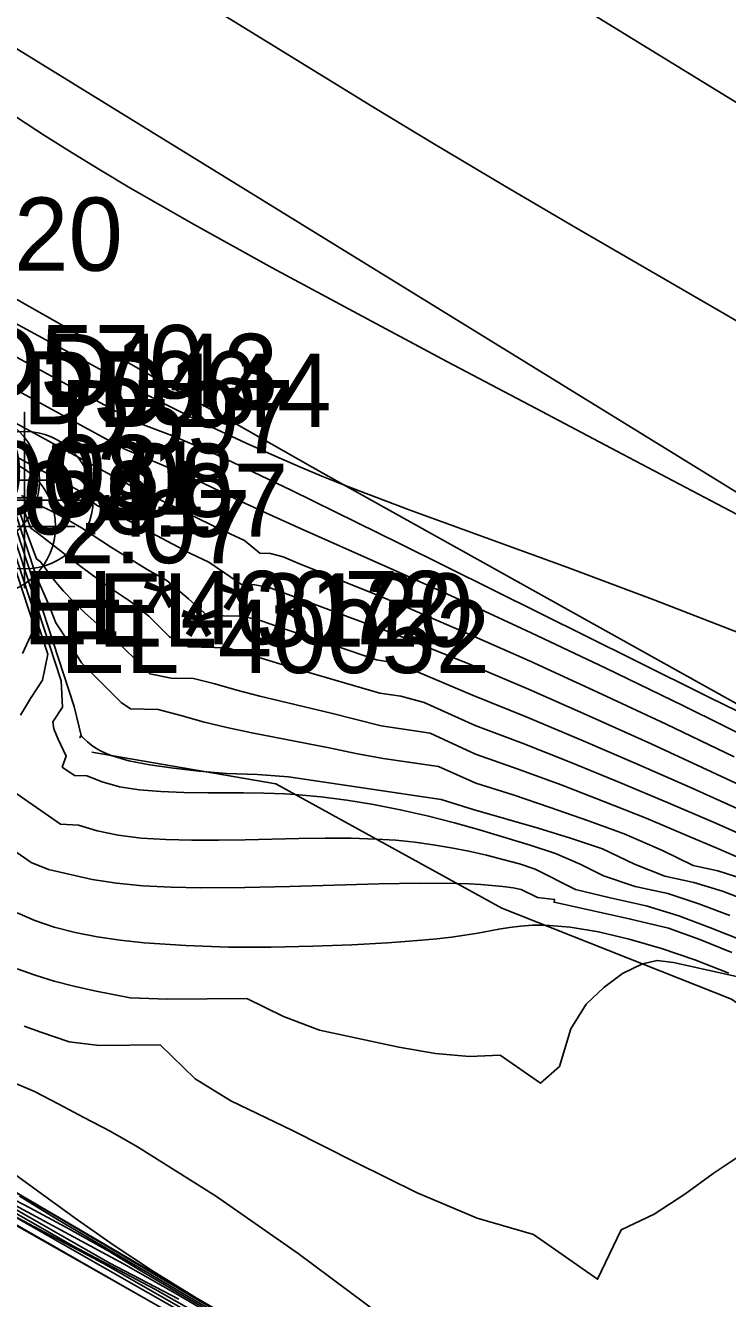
# Model space of a CAD drawing. Extents: x 2356077 to 2359823, y 225951 to 227822.
# Drawn here: x 2357233.67 to 2357257.64, y 226874.84 to 226918.29 of the extents above; entities that cross this region are included whole.
import ezdxf

# ---------------------------------------------------------------- set-up
doc = ezdxf.new("R2010")
doc.units = 0
for name, color, linetype in [('DTM Contours Major', 7, 'Continuous'), ('DTM Contours Minor', 7, 'Continuous'), ('Exist DTM Breakline', 7, 'Continuous'), ('Exist DTM Breakline Cogo Comment', 7, 'Continuous'), ('Exist DTM Breakline Cogo Elevation', 7, 'Continuous'), ('Exist DTM Breakline Cogo Number', 7, 'Continuous'), ('Exist DTM Breakline Cogo Point CELL', 7, 'Continuous'), ('Exist DTM Breakline Underwater', 7, 'Continuous'), ('Exist DTM Breakline Underwater Cogo Comment', 7, 'Continuous'), ('Exist DTM Breakline Underwater Cogo Elevation', 7, 'Continuous'), ('Exist DTM Breakline Underwater Cogo Number', 7, 'Continuous'), ('Exist DTM Breakline Underwater Cogo Point CELL', 7, 'Continuous'), ('Exist DTM Crownline', 7, 'Continuous'), ('Exist DTM Drainline Cogo Comment', 7, 'Continuous'), ('Exist DTM Regular Point Underwater Cogo Elevation', 7, 'Continuous'), ('Exist DTM Regular Point Underwater Cogo Number', 7, 'Continuous'), ('Exist Roads EOP', 7, 'Continuous'), ('Exist Structure Minor Head and End Wall Cogo Comment', 7, 'Continuous'), ('Exist Structure Minor Head and End Wall Cogo Elevation', 7, 'Continuous'), ('Exist Structure Minor Head and End Wall Cogo Number', 7, 'Continuous'), ('Exist Structure Minor Head and End Wall Cogo Point CELL', 7, 'Continuous'), ('PH Exist DTM Breakline', 7, 'Continuous')]:
    doc.layers.add(name, color=color, linetype=linetype)

msp = doc.modelspace()

# ---------------------------------------------------------------- linework, layer by layer
at = {"layer": 'DTM Contours Major'}
for points in [[(2357259.379, 226894.199), (2357257.032, 226895.35), (2357254.467, 226896.62), (2357246.438, 226900.61), (2357242.768, 226902.412), (2357241.175, 226903.182), (2357240.357, 226903.564), (2357239.952, 226903.748), (2357238.667, 226904.296), (2357237.424, 226904.758), (2357230.879, 226908.313)], [(2357258.086, 226890.681), (2357257.192, 226891.086), (2357255.615, 226891.755), (2357253.983, 226892.439), (2357252.322, 226893.12), (2357250.661, 226893.778), (2357249.025, 226894.395), (2357247.279, 226895.175), (2357246.489, 226895.394), (2357245.768, 226895.501), (2357242.718, 226896.389), (2357241.977, 226896.61), (2357240.569, 226897.049), (2357239.237, 226897.085), (2357238.588, 226897.424), (2357237.887, 226898.121), (2357237.225, 226898.649), (2357236.574, 226899.081), (2357235.959, 226899.521), (2357235.376, 226899.96), (2357234.046, 226900.989), (2357233.856, 226901.132), (2357233.621, 226901.724)], [(2357233.499, 226894.751), (2357233.838, 226895.313), (2357234.246, 226895.936), (2357234.435, 226896.825), (2357232.944, 226901.378)], [(2357258.155, 226887.055), (2357257.065, 226887.491), (2357255.983, 226887.896), (2357254.867, 226888.242), (2357253.64, 226888.515), (2357252.457, 226888.802), (2357251.078, 226889.494), (2357250.536, 226889.668), (2357249.973, 226889.822), (2357249.413, 226889.963), (2357248.81, 226890.1), (2357248.203, 226890.221), (2357247.588, 226890.324), (2357246.96, 226890.409), (2357246.313, 226890.475), (2357245.644, 226890.52), (2357244.791, 226890.548), (2357243.907, 226890.551), (2357243.002, 226890.538), (2357241.17, 226890.493), (2357240.264, 226890.476), (2357239.346, 226890.475), (2357238.46, 226890.498), (2357237.62, 226890.553), (2357236.836, 226890.649), (2357236.12, 226890.794), (2357235.484, 226890.997), (2357234.861, 226891.021), (2357233.077, 226892.261)], [(2357245.841, 226874.248), (2357242.983, 226876.373), (2357240.158, 226878.343), (2357237.493, 226880.018), (2357236.559, 226880.544), (2357235.665, 226881.019), (2357234.805, 226881.464), (2357233.979, 226881.899), (2357233.205, 226882.233)], [(2357238.268, 226874.546), (2357229.529, 226879.532)], [(2357240.511, 226874.001), (2357238.784, 226875.014), (2357237.012, 226876.025), (2357233.304, 226878.019)]]:
    msp.add_lwpolyline(points, dxfattribs=at)
at = {"layer": 'DTM Contours Minor'}
for points in [[(2357258.815, 226901.155), (2357254.058, 226903.658), (2357251.108, 226905.209), (2357248.057, 226906.82), (2357245.016, 226908.442), (2357242.096, 226910.021), (2357239.409, 226911.507), (2357238.293, 226912.138), (2357237.237, 226912.748), (2357236.23, 226913.344), (2357235.262, 226913.935), (2357234.32, 226914.53), (2357233.395, 226915.136), (2357232.729, 226915.587), (2357231.377, 226916.526), (2357229.955, 226917.523), (2357229.2, 226918.046), (2357226.653, 226919.767)], [(2357260.038, 226906.976), (2357257.54, 226908.44), (2357252.514, 226911.361), (2357250.026, 226912.818), (2357247.581, 226914.271), (2357245.68, 226915.422), (2357240.031, 226918.889)], [(2357258.266, 226897.467), (2357255.166, 226898.675), (2357252.154, 226899.796), (2357246.767, 226901.757), (2357244.581, 226902.586), (2357243.794, 226902.902), (2357243.061, 226903.209), (2357241.967, 226903.688), (2357241.2, 226904.036), (2357239.517, 226904.819), (2357237.877, 226905.644), (2357230.432, 226909.689)], [(2357238.901, 226874.819), (2357236.525, 226876.052), (2357229.684, 226879.956), (2357224.75, 226882.878), (2357223.73, 226883.469), (2357223.037, 226884.013), (2357219.781, 226885.873), (2357219.03, 226886.387), (2357229.069, 226899.479), (2357230.892, 226901.945), (2357230.985, 226902.237), (2357231.039, 226902.209), (2357229.028, 226903.4), (2357226.593, 226904.852), (2357225.975, 226905.198), (2357219.406, 226908.954)], [(2357258.802, 226893.741), (2357256.134, 226895.069), (2357253.488, 226896.352), (2357250.939, 226897.559), (2357248.564, 226898.658), (2357246.438, 226899.618), (2357242.976, 226901.147), (2357241.872, 226901.649), (2357241.06, 226902.031), (2357239.718, 226902.675), (2357239.276, 226902.88), (2357238.834, 226903.079), (2357237.059, 226903.823), (2357231.766, 226906.699)], [(2357257.871, 226893.324), (2357255.546, 226894.436), (2357253.199, 226895.534), (2357250.898, 226896.586), (2357248.711, 226897.558), (2357246.705, 226898.419), (2357245.525, 226898.907), (2357242.948, 226899.951), (2357242.473, 226900.146), (2357242.041, 226900.269), (2357241.667, 226900.278), (2357241.145, 226900.707), (2357240.175, 226901.166), (2357238.617, 226901.93), (2357238.12, 226902.167), (2357237.632, 226902.388), (2357236.995, 226902.724), (2357232.432, 226905.204)], [(2357259.072, 226891.891), (2357257.097, 226892.816), (2357255.032, 226893.766), (2357252.931, 226894.714), (2357250.848, 226895.629), (2357248.837, 226896.484), (2357246.232, 226897.539), (2357245.579, 226897.777), (2357243.71, 226898.468), (2357242.55, 226898.897), (2357241.99, 226899.109), (2357241.498, 226899.197), (2357241.041, 226899.209), (2357240.464, 226899.608), (2357239.933, 226899.965), (2357239.302, 226900.269), (2357238.698, 226900.578), (2357237.046, 226901.454), (2357236.55, 226901.701), (2357236.096, 226901.911), (2357235.525, 226902.39), (2357233.193, 226903.657)], [(2357258.888, 226891.152), (2357256.355, 226892.285), (2357254.515, 226893.095), (2357252.639, 226893.905), (2357250.767, 226894.69), (2357248.939, 226895.427), (2357247.082, 226896.209), (2357246.269, 226896.533), (2357245.655, 226896.637), (2357244.217, 226897.122), (2357242.873, 226897.568), (2357242.205, 226897.795), (2357241.56, 226898.02), (2357240.985, 226898.124), (2357239.876, 226898.154), (2357239.238, 226898.717), (2357238.493, 226899.344), (2357237.824, 226899.722), (2357237.195, 226900.103), (2357236.61, 226900.474), (2357235.577, 226901.137), (2357235.093, 226901.428), (2357234.869, 226901.554), (2357234.654, 226901.668), (2357234.448, 226901.769), (2357234.248, 226901.86), (2357233.92, 226902.126), (2357233.798, 226902.161), (2357233.712, 226902.153), (2357233.53, 226902.245)], [(2357258.196, 226889.812), (2357257.251, 226890.22), (2357256.331, 226890.602), (2357254.862, 226891.235), (2357253.42, 226891.805), (2357251.958, 226892.367), (2357250.492, 226892.908), (2357249.037, 226893.413), (2357247.494, 226894.132), (2357246.662, 226894.262), (2357245.816, 226894.388), (2357244.107, 226894.81), (2357241.671, 226895.398), (2357240.888, 226895.6), (2357240.137, 226895.811), (2357239.411, 226895.994), (2357238.643, 226896.014), (2357237.912, 226896.157), (2357236.557, 226897.504), (2357236.112, 226897.864), (2357235.694, 226898.237), (2357235.305, 226898.622), (2357234.971, 226898.984), (2357234.654, 226899.35), (2357234.185, 226899.983), (2357234.046, 226900.081), (2357233.681, 226901.057), (2357233.456, 226901.746)], [(2357233.569, 226896.857), (2357233.976, 226897.744), (2357232.803, 226901.326)], [(2357257.719, 226887.91), (2357256.666, 226888.312), (2357255.602, 226888.656), (2357254.487, 226888.904), (2357253.413, 226889.259), (2357252.609, 226889.661), (2357251.766, 226890.022), (2357250.9, 226890.306), (2357250.037, 226890.577), (2357249.177, 226890.834), (2357248.317, 226891.073), (2357247.39, 226891.308), (2357246.466, 226891.516), (2357245.55, 226891.695), (2357244.645, 226891.843), (2357243.755, 226891.957), (2357242.883, 226892.036), (2357242.522, 226892.058), (2357241.811, 226892.086), (2357241.112, 226892.097), (2357239.909, 226892.101), (2357239.079, 226892.109), (2357238.289, 226892.137), (2357237.553, 226892.198), (2357236.883, 226892.306), (2357236.292, 226892.475), (2357235.766, 226892.672), (2357235.344, 226892.683), (2357234.926, 226892.973), (2357235.057, 226893.344), (2357234.769, 226893.947), (2357234.642, 226894.281), (2357234.601, 226894.524), (2357234.928, 226895.022), (2357234.888, 226895.923), (2357233.08, 226901.445)], [(2357258.455, 226888.36), (2357257.472, 226888.744), (2357256.495, 226889.035), (2357255.497, 226889.257), (2357254.469, 226889.665), (2357253.379, 226890.186), (2357252.285, 226890.543), (2357251.179, 226890.885), (2357248.958, 226891.528), (2357247.866, 226891.871), (2357242.65, 226892.646), (2357241.591, 226892.722), (2357240.53, 226892.752), (2357239.596, 226892.838), (2357238.719, 226892.933), (2357237.915, 226893.048), (2357237.201, 226893.192), (2357236.593, 226893.375), (2357236.406, 226893.452), (2357236.232, 226893.535), (2357236.072, 226893.626), (2357235.924, 226893.726), (2357235.786, 226893.834), (2357235.657, 226893.953), (2357235.606, 226894.004), (2357235.565, 226894.039), (2357235.527, 226893.983), (2357235.574, 226894.054), (2357235.334, 226895.043), (2357233.199, 226901.563)], [(2357258.17, 226889.16), (2357257.317, 226889.43), (2357256.473, 226889.618), (2357255.42, 226890.123), (2357254.117, 226890.697), (2357252.86, 226891.155), (2357251.592, 226891.601), (2357250.318, 226892.027), (2357249.046, 226892.423), (2357247.768, 226892.992), (2357245.889, 226893.271), (2357244.954, 226893.443), (2357244.042, 226893.628), (2357241.397, 226894.142), (2357240.547, 226894.322), (2357239.736, 226894.517), (2357238.969, 226894.738), (2357238.201, 226894.94), (2357237.257, 226894.965), (2357236.942, 226895.183), (2357235.586, 226896.531), (2357235.173, 226897.198), (2357234.711, 226897.893), (2357234.465, 226898.51), (2357234.044, 226899.467), (2357233.332, 226901.641)], [(2357257.79, 226886.644), (2357256.698, 226887.085), (2357255.624, 226887.48), (2357254.289, 226887.792), (2357251.721, 226888.363), (2357251.74, 226888.456), (2357251.152, 226888.521), (2357250.592, 226888.802), (2357250.321, 226888.851), (2357249.966, 226888.896), (2357249.6, 226888.933), (2357249.22, 226888.964), (2357248.822, 226888.987), (2357248.404, 226889.004), (2357247.139, 226889.016), (2357245.737, 226888.992), (2357242.702, 226888.899), (2357241.159, 226888.863), (2357239.659, 226888.855), (2357238.645, 226888.877), (2357237.682, 226888.927), (2357236.778, 226889.013), (2357235.941, 226889.14), (2357234.45, 226889.483), (2357233.858, 226889.722), (2357231.329, 226891.479)], [(2357257.688, 226885.942), (2357256.531, 226886.393), (2357255.388, 226886.783), (2357254.282, 226887.103), (2357253.237, 226887.347), (2357252.273, 226887.507), (2357251.415, 226887.576), (2357250.981, 226887.574), (2357250.578, 226887.545), (2357250.2, 226887.498), (2357249.836, 226887.438), (2357249.116, 226887.306), (2357248.675, 226887.235), (2357248.212, 226887.172), (2357247.721, 226887.117), (2357247.197, 226887.067), (2357246.634, 226887.021), (2357246.027, 226886.979), (2357244.814, 226886.91), (2357243.48, 226886.857), (2357242.064, 226886.828), (2357240.607, 226886.833), (2357239.147, 226886.881), (2357237.725, 226886.981), (2357236.903, 226887.07), (2357236.113, 226887.185), (2357235.362, 226887.331), (2357234.654, 226887.513), (2357233.994, 226887.735), (2357233.387, 226888.001)], [(2357258.155, 226885.777), (2357255.801, 226886.301), (2357255.237, 226886.375), (2357254.739, 226886.26), (2357254.057, 226885.925), (2357253.424, 226885.446), (2357252.812, 226884.888), (2357252.288, 226884.037), (2357251.902, 226882.751), (2357251.257, 226882.186), (2357249.883, 226883.141), (2357248.827, 226883.091), (2357247.67, 226883.2), (2357246.424, 226883.419), (2357243.705, 226883.992), (2357242.479, 226884.467), (2357241.23, 226885.08), (2357238.515, 226885.049), (2357237.247, 226885.096), (2357236.027, 226885.338), (2357235.323, 226885.498), (2357234.645, 226885.673), (2357233.997, 226885.868), (2357233.38, 226886.085)], [(2357258.104, 226879.736), (2357257.158, 226879.107), (2357256.18, 226878.398), (2357255.141, 226877.72), (2357254.012, 226877.185), (2357253.207, 226875.493), (2357251.017, 226877.023), (2357249.092, 226877.58), (2357247.043, 226878.444), (2357244.923, 226879.486), (2357242.783, 226880.574), (2357240.678, 226881.578), (2357239.469, 226882.331), (2357238.265, 226883.498), (2357236.183, 226883.473), (2357235.166, 226883.595), (2357234.189, 226883.926), (2357233.624, 226884.127)], [(2357247.889, 226869.874), (2357230.089, 226880.364)], [(2357243.5, 226872.067), (2357238.081, 226875.159), (2357235.263, 226876.645), (2357229.64, 226879.853)], [(2357249.67, 226868.677), (2357237.633, 226875.771), (2357236.491, 226876.467), (2357235.169, 226877.205), (2357233.813, 226877.936), (2357232.345, 226878.694)], [(2357241.876, 226873.478), (2357239.502, 226874.855), (2357238.012, 226875.782), (2357236.669, 226876.672), (2357235.45, 226877.523), (2357234.331, 226878.33), (2357233.288, 226879.09)], [(2357248.787, 226869.271), (2357234.761, 226877.537), (2357233.464, 226878.324)], [(2357245.888, 226870.576), (2357236.329, 226876.031), (2357233.252, 226877.664)], [(2357248.292, 226869.077), (2357233.41, 226877.569)]]:
    msp.add_lwpolyline(points, dxfattribs=at)
at = {"layer": 'Exist DTM Breakline'}
msp.add_lwpolyline([(2357271.839, 226810.793), (2357233.688, 226822.752), (2357256.15, 226865.111), (2357219.602, 226886.502), (2357232.348, 226901.185)], dxfattribs=at)
at = {"layer": 'Exist DTM Breakline Cogo Point CELL'}
msp.add_lwpolyline([(2357232.348, 226904.185), (2357232.348, 226898.185), (2357232.348, 226901.185), (2357235.348, 226901.185), (2357229.348, 226901.185)], dxfattribs=at)
msp.add_circle((2357232.348, 226901.185), 2.344, dxfattribs=at)
at = {"layer": 'Exist DTM Breakline Underwater'}
msp.add_lwpolyline([(2357271.485, 226810.176), (2357230.992, 226822.359), (2357255.147, 226864.969), (2357217.975, 226886.043), (2357231.073, 226902.169)], dxfattribs=at)
at = {"layer": 'Exist DTM Breakline Underwater Cogo Point CELL'}
msp.add_lwpolyline([(2357231.073, 226905.169), (2357231.073, 226899.169), (2357231.073, 226902.169), (2357234.073, 226902.169), (2357228.073, 226902.169)], dxfattribs=at)
at = {"layer": 'Exist DTM Crownline'}
msp.add_lwpolyline([(2357542.756, 226741.609), (2357459.889, 226792.427), (2357374.177, 226844.74), (2357291.426, 226895.083), (2357208.118, 226946.275), (2357125.882, 226996.539), (2357045.017, 227045.595), (2356966.337, 227093.498), (2356883.413, 227143.712), (2356799.704, 227194.618), (2356722.637, 227241.528), (2356636.765, 227293.74), (2356553.053, 227344.465), (2356470.397, 227394.758), (2356383.201, 227447.638), (2356299.889, 227498.478), (2356223.248, 227545.375)], dxfattribs=at)
at = {"layer": 'Exist Roads EOP'}
msp.add_lwpolyline([(2357548.158, 226751.097), (2357551.518, 226748.955), (2357539.932, 226730.044), (2357536.732, 226732.588), (2357457.094, 226780.918), (2357368.575, 226834.971), (2357285.95, 226885.112), (2357202.56, 226936.462), (2357119.743, 226986.718), (2357040.047, 227034.838), (2356959.55, 227083.993), (2356876.77, 227134.388), (2356794.33, 227184.148), (2356716.529, 227232.438), (2356632.17, 227283.448), (2356547.589, 227334.799), (2356465.16, 227384.805), (2356376.528, 227438.798), (2356293.908, 227488.913), (2356217.843, 227535.566)], dxfattribs=at)
at = {"layer": 'Exist Structure Minor Head and End Wall Cogo Point CELL'}
for points in [[(2357228.808, 226902.763), (2357234.808, 226902.763), (2357231.808, 226902.763), (2357231.808, 226905.763), (2357231.808, 226899.763)], [(2357230.633, 226902.085), (2357236.633, 226902.085), (2357233.633, 226902.085), (2357233.633, 226905.085), (2357233.633, 226899.085)]]:
    msp.add_lwpolyline(points, dxfattribs=at)
for centre in [(2357231.808, 226902.763), (2357233.633, 226902.085)]:
    msp.add_circle(centre, 2.344, dxfattribs=at)
at = {"layer": 'PH Exist DTM Breakline'}
for points in [[(2357134.751, 226970.426), (2357158.028, 226955.6), (2357176.952, 226945.122), (2357197.905, 226932.262), (2357212.892, 226921.066), (2357229.01, 226911.408), (2357243.825, 226903.007), (2357264.516, 226891.487), (2357285.525, 226878.969), (2357309.065, 226864.903), (2357332.833, 226850.108), (2357352.43, 226838.187), (2357373.686, 226825.25), (2357394.277, 226813), (2357414.012, 226801.184), (2357434.963, 226788.955), (2357455.092, 226776.87), (2357475.043, 226763.829)], [(2357329.327, 226839.832), (2357322.093, 226843.761), (2357315.282, 226847.511), (2357308.493, 226851.773), (2357300.459, 226857.57), (2357292.502, 226862.082), (2357284.62, 226866.884), (2357274.115, 226873.82), (2357265.28, 226880.04), (2357257.777, 226885.056), (2357249.936, 226888.163), (2357242.214, 226892.404), (2357235.933, 226893.489)]]:
    msp.add_lwpolyline(points, dxfattribs=at)

# ---------------------------------------------------------------- texts
at = {"layer": 'Exist DTM Breakline Cogo Comment'}
msp.add_text('EL*40052', height=2.5, dxfattribs=at).set_placement((2357234.848, 226896.185))
at = {"layer": 'Exist DTM Breakline Cogo Elevation'}
msp.add_text('2.07', height=2.5, dxfattribs=at).set_placement((2357234.848, 226899.935))
at = {"layer": 'Exist DTM Breakline Cogo Number'}
msp.add_text('D597', height=2.5, dxfattribs=at).set_placement((2357234.848, 226903.685))
at = {"layer": 'Exist DTM Breakline Underwater Cogo Comment'}
msp.add_text('EL*40072', height=2.5, dxfattribs=at).set_placement((2357233.573, 226897.169))
at = {"layer": 'Exist DTM Breakline Underwater Cogo Elevation'}
msp.add_text('0.81', height=2.5, dxfattribs=at).set_placement((2357233.573, 226900.919))
at = {"layer": 'Exist DTM Breakline Underwater Cogo Number'}
msp.add_text('D596', height=2.5, dxfattribs=at).set_placement((2357233.573, 226904.669))
at = {"layer": 'Exist DTM Drainline Cogo Comment'}
msp.add_text('BL*40031', height=2.5, dxfattribs=at).set_placement((2357225.127, 226901.595))
msp.add_text('BL*40031', height=2.5, dxfattribs=at).set_placement((2357225.127, 226901.595))
at = {"layer": 'Exist DTM Regular Point Underwater Cogo Elevation'}
msp.add_text('0.08', height=2.5, dxfattribs=at).set_placement((2357231.76, 226901.812))
at = {"layer": 'Exist DTM Regular Point Underwater Cogo Number'}
msp.add_text('D570', height=2.5, dxfattribs=at).set_placement((2357231.76, 226905.562))
at = {"layer": 'Exist Structure Minor Head and End Wall Cogo Comment'}
for s, p in [('CONC BL*3120', (2357213.397, 226909.915)), ('EL*3120', (2357236.133, 226897.085))]:
    msp.add_text(s, height=2.5, dxfattribs=at).set_placement(p)
at = {"layer": 'Exist Structure Minor Head and End Wall Cogo Elevation'}
for s, p in [('5.08', (2357234.308, 226901.514)), ('4.07', (2357236.133, 226900.835))]:
    msp.add_text(s, height=2.5, dxfattribs=at).set_placement(p)
at = {"layer": 'Exist Structure Minor Head and End Wall Cogo Number'}
for s, p in [('D143', (2357234.308, 226905.264)), ('D144', (2357236.133, 226904.585))]:
    msp.add_text(s, height=2.5, dxfattribs=at).set_placement(p)

doc.saveas('drawing.dxf')
